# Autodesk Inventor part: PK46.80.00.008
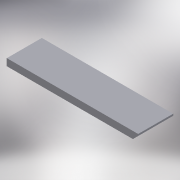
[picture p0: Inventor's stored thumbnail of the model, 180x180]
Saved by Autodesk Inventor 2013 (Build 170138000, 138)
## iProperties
Shininess: 64.0
Length Units: 11269
Angle Units: 11279
Time Units: 11290
Mass Units: 11283
Length Display Precision: 3
Angle Display Precision: 2
Compacted: True
Part Number: PK46.80.00.008
Document SubType Name: Modeling
Created: 2005-01
Material: Steel, Mild
Designer: SAlex
Manufacturer: Standard
Standards Organization: Custom
Density: 7.86 g/cm^3
Mass: 2972.97 g
Surface Area: 594.536 cm^2
Volume: 378.24 cm^3
Density: 0.0
Volumn: 0.0
Area: 0.0
PropertySet Name: Model Information
Control State: 0
Master: False
Checked Out: False
Checked Out Date: 2008-10-15
Last Check In Date: 2008-10-15
Author: SAlex
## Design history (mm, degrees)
sketch "Sketch1"
  geometry: L1 (0, 0)-(300, 0); L2 (300, 0)-(300, 80); L3 (300, 80)-(0, 80); L4 (0, 80)-(0, 0)
  constraints: 8 end point, 2 parallel, 1 horizontal, 1 perpendicular, 1 other
  dimensions: "d0" = 300 distance of L1.start L1.end; "d1" = 80 distance of L3.end L1.start
extrude "Extrusion1" new body sketch "Sketch1" distance "d2" = 16; taper "d3" = 0 deg
chamfer "Chamfer1" distance "d4" = 12; stored, may be unused: second distance "d5" = 2, angle "d6" = 45 deg
body "Solid1"
